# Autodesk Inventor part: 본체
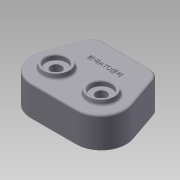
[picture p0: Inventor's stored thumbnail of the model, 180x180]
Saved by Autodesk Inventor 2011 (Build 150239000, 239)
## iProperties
Created: 2014-12
Part Number: 본체
Document SubType Name: Modeling
Designer: SDA
Density: 2.71 g/cm^3
Material: 알루미늄-6061
Mass: 613.439 g
Surface Area: 665.18 cm^2
Volume: 226.361 cm^3
Author: SDA
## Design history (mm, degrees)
sketch "스케치1"
  geometry: L1 (-34.162, 36)-(34.162, 36); L2 (0, 0)-(-32.527, -32.527); L3 (0, 0)-(32.527, -32.527); L4 (0, 60.781)-(0, -67.298); L5 (-51.181, 23.862)-(-66.565, -20.803); L6 (51.181, 23.862)-(66.565, -20.803); L7 (-32.527, -68.527)-(32.527, -68.527); A1 r 46 centre (0, 0) between (-32.527, -32.527) and (32.527, -32.527); A2 r 18 centre (-34.162, 18) between (-34.162, 36) and (-51.181, 23.862); A3 r 18 centre (34.162, 18) between (51.181, 23.862) and (34.162, 36); A4 r 36 centre (-32.527, -32.527) between (-66.565, -20.803) and (-32.527, -68.527); A5 r 36 centre (32.527, -32.527) between (32.527, -68.527) and (66.565, -20.803); 4 further points
  constraints: 14 end point, 10 point on circle, 7 tangent, 5 centre point, 4 coincident, 4 point on line, 2 perpendicular, 1 equal radius, 1 horizontal, 1 midpoint, 1 vertical alignment
  dimensions: "d0" = 94 distance of point (-47, 36) point (47, 36); "d4" = 92 diameter of A1; "d5" = 36 distance from line of point (0, 0) L1; "d7" = 45 deg angle of L4 L2; "d8" = 45 deg angle of L3 L4; "d12" = 18 radius of A2; "d13" = 36 radius of A5; "d14" = 36 radius of A4
extrude "돌출1" new body sketch "스케치1" distance "d15" = 44; taper "d16" = 0 deg
feature "쉘1" dims "d17" = 5
sketch "스케치2"
  geometry: C1 r 24 at (34.162, -31); C2 r 24 at (1.635, -63.527); C3 r 24 at (66.689, -63.527); A1 r 31 centre (1.635, -63.527) between (-27.675, -53.432) and (1.635, -94.527) reference; A2 r 31 centre (66.689, -63.527) between (66.689, -94.527) and (95.999, -53.432) reference; 1 further point
  constraints: 3 centre point, 3 coincident
  dimensions: "d18" = 48 diameter of C1; "d19" = 48 diameter of C2; "d20" = 48 diameter of C3
extrude "돌출2" join sketch "스케치2" distance "d21" = 16; taper "d22" = 0 deg
sketch "스케치3"
  geometry: L1 (-61.837, -22.432)-(-46.453, 22.233) reference; L2 (46.453, 22.233)-(61.837, -22.432) reference; L3 (32.527, -63.527)-(-32.527, -63.527) reference; L4 (-66.565, -20.803)-(-51.181, 23.862) reference; L5 (32.527, -68.527)-(-32.527, -68.527) reference; L6 (51.181, 23.862)-(66.565, -20.803) reference; L7 (-34.162, 36)-(34.162, 36) reference; L8 (-72.125, 7)-(77.004, 7); L9 (0, 60.781)-(0, -67.298) reference; L10 (-32.527, -63.527)-(32.527, -63.527) reference; A1 r 8 centre (-51.7, 7) between (-58.461, 2.724) and (-54.394, 14.533); A2 r 8 centre (0, -63.527) between (6.245, -68.527) and (-6.245, -68.527); A3 r 8 centre (51.7, 7) between (54.394, 14.533) and (58.461, 2.724); 1 further point
  constraints: 10 point on line, 6 point on circle, 3 centre point, 2 end point, 1 midpoint, 1 parallel
  dimensions: "d23" = 29 distance between parallel lines of L8 L7; "d24" = 16 diameter of A1; "d25" = 16 diameter of A2; "d26" = 16 diameter of A3
extrude "돌출3" join sketch "스케치3" stored distance "d27" = 11; taper "d28" = 0 deg
hole "Hole1" diameter "d31" = 35; stored, may be unused: countersink angle "d35" = 90 deg, drill point angle "d37" = 0 deg; dims "d29" = 10, "d30" = 10, "d32" = 6, "d33" = 4, "d34" = 2, "d36" = 11
hole "Hole2" diameter "d40" = 35; stored, may be unused: countersink angle "d44" = 90 deg, drill point angle "d46" = 0 deg; dims "d38" = 10, "d39" = 10, "d41" = 6, "d42" = 4, "d43" = 2, "d45" = 11
hole "Hole3" diameter "d49" = 15.5; stored, may be unused: countersink angle "d53" = 90 deg, drill point angle "d55" = 0 deg; dims "d47" = 10, "d48" = 10, "d50" = 6, "d51" = 4, "d52" = 2, "d54" = 10
hole "Hole4" diameter "d58" = 15.5; stored, may be unused: countersink angle "d62" = 90 deg, drill point angle "d64" = 0 deg; dims "d56" = 10, "d57" = 10, "d59" = 6, "d60" = 4, "d61" = 2, "d63" = 10
sketch "스케치4"
  geometry: C1 r 20 at (-32.527, -32.527); C2 r 20 at (32.527, -32.527); A1 r 36 centre (32.527, -32.527) between (32.527, -68.527) and (66.565, -20.803) reference; A2 r 36 centre (-32.527, -32.527) between (-66.565, -20.803) and (-32.527, -68.527) reference; 1 further point
  constraints: 2 centre point, 2 coincident
  dimensions: "d65" = 40 diameter of C1; "d66" = 40 diameter of C2
extrude "돌출4" join sketch "스케치4" distance "d67" = 7; taper "d68" = -10 deg
hole "Hole5" diameter "d71" = 30; stored, may be unused: countersink angle "d75" = 90 deg, drill point angle "d77" = 0 deg; dims "d69" = 10, "d70" = 10, "d72" = 6, "d73" = 4, "d74" = 2, "d76" = 7
hole "Hole6" diameter "d80" = 30; stored, may be unused: countersink angle "d84" = 90 deg, drill point angle "d86" = 0 deg; dims "d78" = 10, "d79" = 10, "d81" = 6, "d82" = 4, "d83" = 2, "d85" = 7
hole "Hole7" diameter "d89" = 40; stored, may be unused: countersink angle "d93" = 90 deg, drill point angle "d95" = 0 deg; dims "d87" = 10, "d88" = 10, "d90" = 6, "d91" = 4, "d92" = 2, "d94" = 12
hole "Hole8" diameter "d98" = 20; stored, may be unused: countersink angle "d102" = 90 deg, drill point angle "d104" = 0 deg; dims "d96" = 10, "d97" = 10, "d99" = 6, "d100" = 4, "d101" = 2, "d103" = 3
fillet "모깎기1" dims "d105" = 3
hole "Hole9" diameter "d108" = 4.134; stored, may be unused: countersink angle "d112" = 90 deg, drill point angle "d114" = 118 deg; dims "d106" = 10, "d107" = 10, "d109" = 20, "d110" = 4, "d111" = 2, "d113" = 23
hole "Hole10" diameter "d117" = 4.134; stored, may be unused: countersink angle "d121" = 90 deg, drill point angle "d123" = 118 deg; dims "d115" = 10, "d116" = 10, "d118" = 20, "d119" = 4, "d120" = 2, "d122" = 23
hole "Hole11" diameter "d126" = 4.134; stored, may be unused: countersink angle "d130" = 90 deg, drill point angle "d132" = 118 deg; dims "d124" = 10, "d125" = 10, "d127" = 20, "d128" = 4, "d129" = 2, "d131" = 23
chamfer "모따기1" distance "d136" = 1; stored, may be unused: second distance "d137" = 2, angle "d138" = 45 deg
sketch "스케치5"
  geometry: 1 further point
sketch "스케치6"
  geometry: L1 (-20.143, -31.564)-(-27.675, -53.432) reference; L2 (1.635, -94.527)-(26.162, -94.527) reference; L3 (42.162, -94.527)-(66.689, -94.527) reference; L4 (95.999, -53.432)-(88.467, -31.564) reference; L5 (83.257, -16.436)-(80.615, -8.767) reference; L6 (68.324, 0)-(0, 0) reference; L7 (-12.291, -8.767)-(-14.933, -16.436) reference; A1 r 8 centre (-17.538, -24) between (-20.143, -31.564) and (-14.933, -16.436) reference; A2 r 31 centre (1.635, -63.527) between (-27.675, -53.432) and (1.635, -94.527) reference; A3 r 8 centre (34.162, -94.527) between (42.162, -94.527) and (26.162, -94.527) reference; A4 r 31 centre (66.689, -63.527) between (66.689, -94.527) and (95.999, -53.432) reference; A5 r 8 centre (85.862, -24) between (83.257, -16.436) and (88.467, -31.564) reference; A6 r 13 centre (68.324, -13) between (80.615, -8.767) and (68.324, 0) reference; A7 r 13 centre (0, -13) between (0, 0) and (-12.291, -8.767) reference; A8 r 24 centre (34.162, -31) between (55.273, -42.416) and (13.051, -42.416) reference; A9 r 24 centre (66.689, -63.527) between (45.578, -52.111) and (55.273, -42.416) reference; A10 r 24 centre (34.162, -31) between (22.746, -52.111) and (45.578, -52.111) reference; A11 r 24 centre (1.635, -63.527) between (13.051, -42.416) and (22.746, -52.111) reference
extrude "돌출5" join sketch "스케치6" distance "d139" = 5; taper "d140" = 0 deg
fillet "모깎기3" dims "d141" = 3
sketch "스케치10"
  geometry: 1 further point
fillet "모깎기4" dims "d142" = 0.3, "d143" = 0.1
sketch "스케치11"
  geometry: L1 (34.162, 36)-(-34.162, 36) reference; 2 further points
  constraints: 1 vertical alignment, 1 other
  dimensions: "d144" = 30 distance from line of point (0, 6) L1
feature "엠보싱1" sketch "스케치11" dims "d145" = 1, "d146" = 0
node "솔리드1"
other parameters: "d10" = 72, "d11" = 72
